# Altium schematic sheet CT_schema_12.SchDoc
size 386 x 278 mm
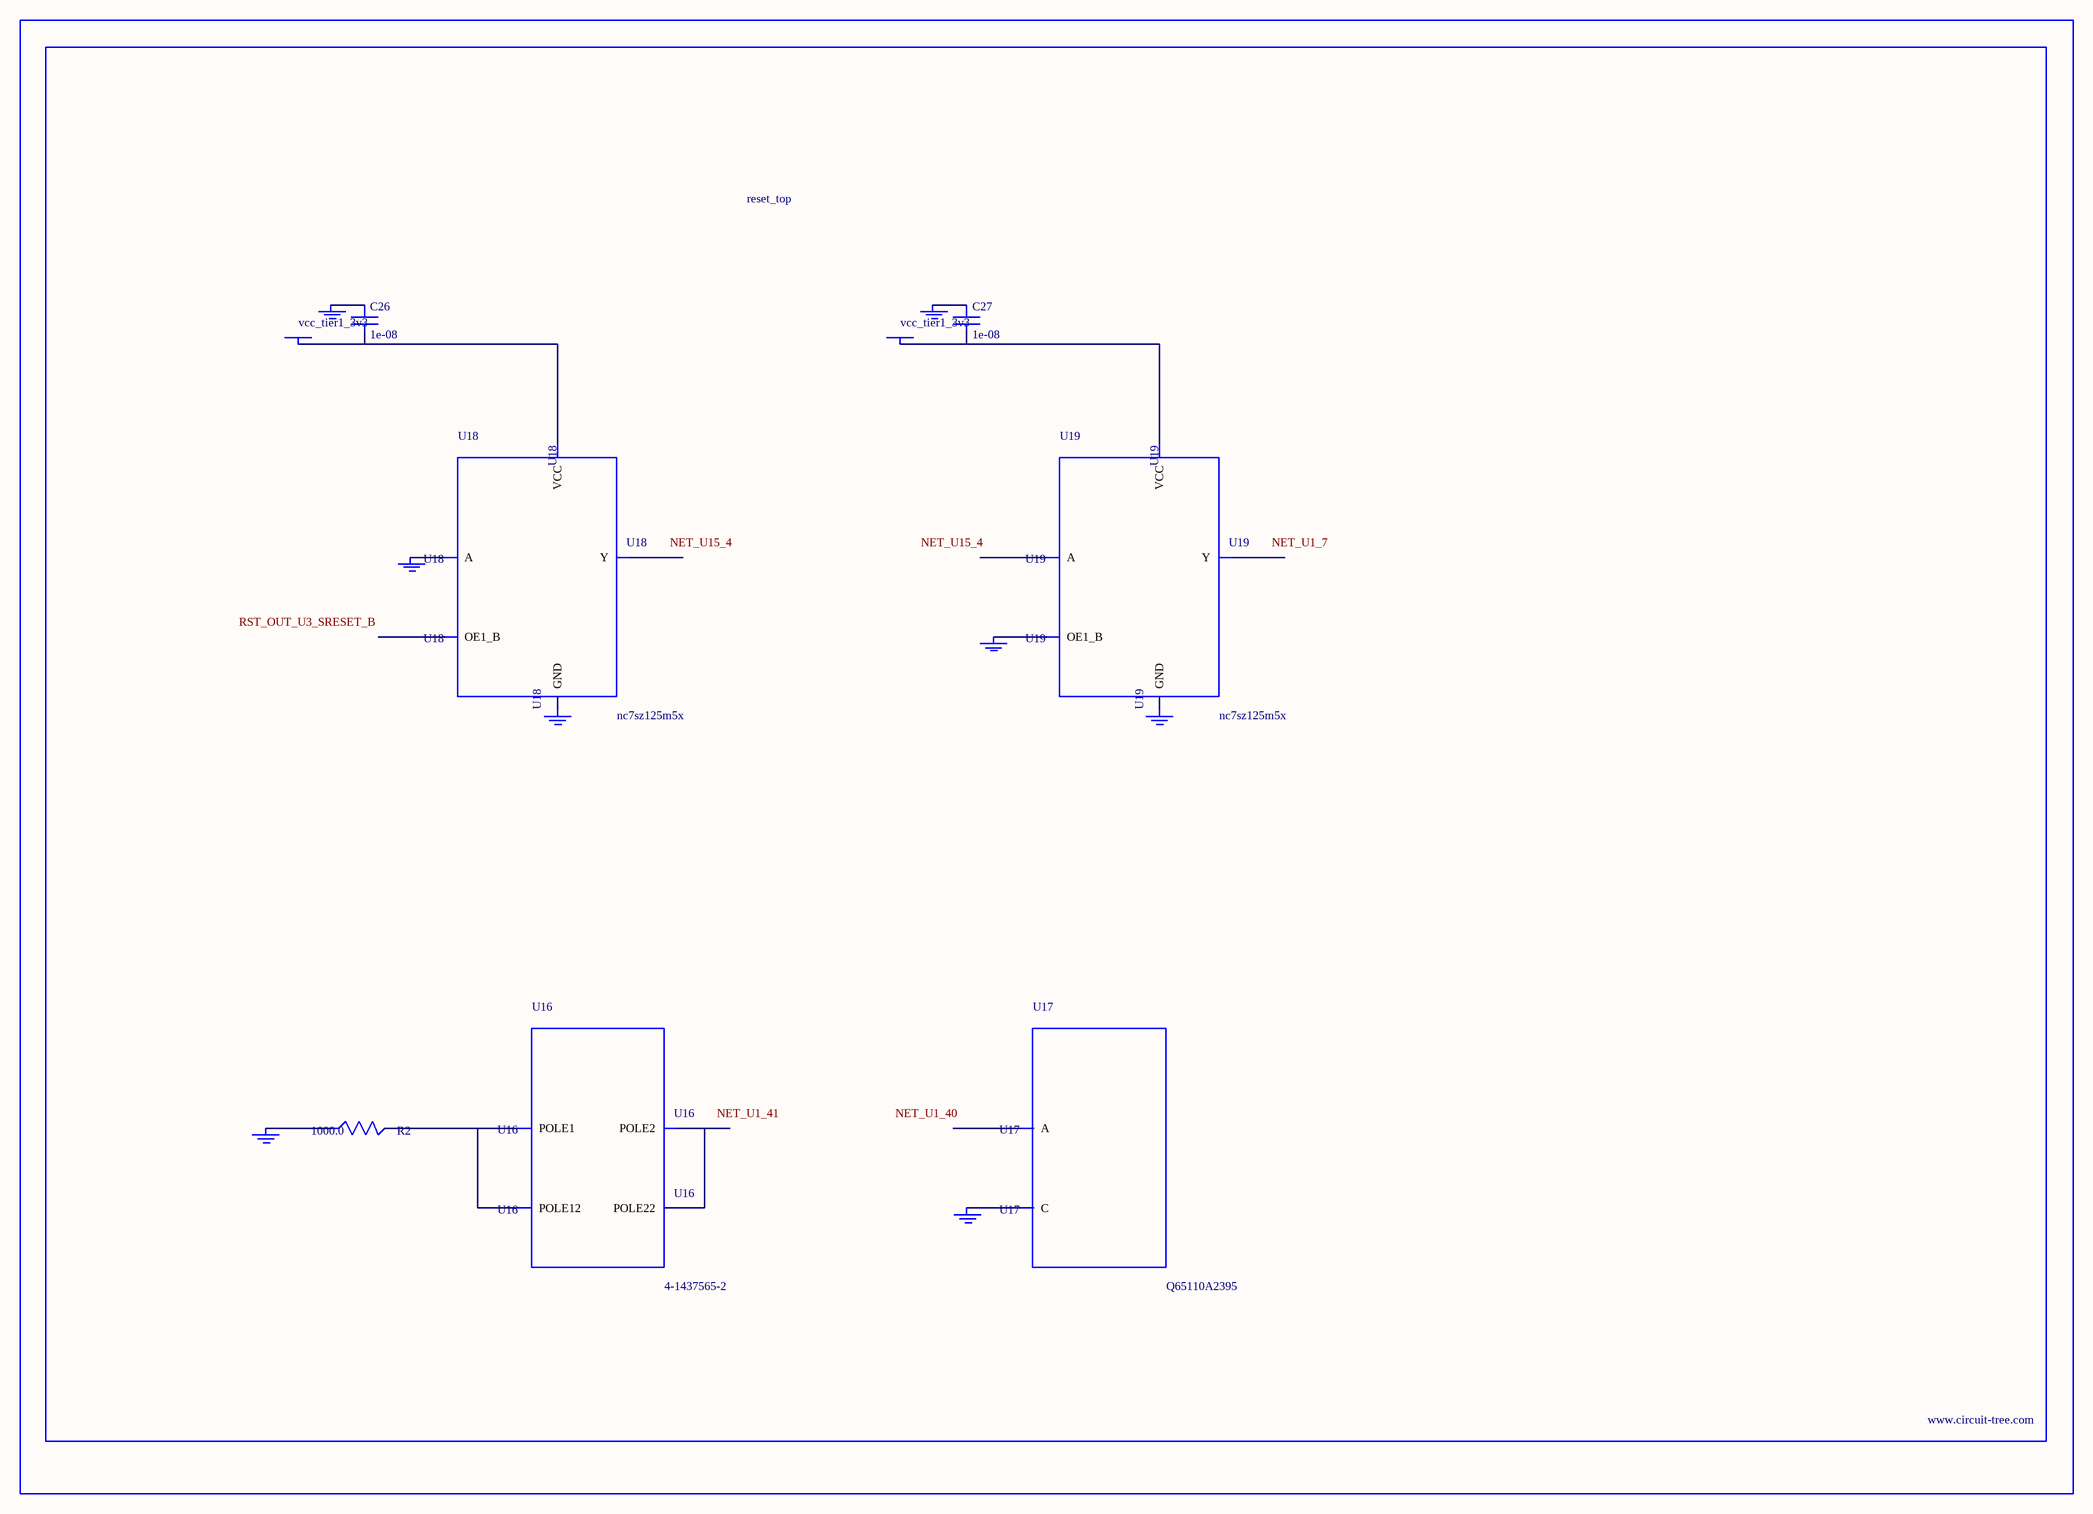
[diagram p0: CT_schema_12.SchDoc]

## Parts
BORDER11  (no value)
C26  1e-08  [C0402]
C27  1e-08  [C0402]
GND_INSTANCE_11_0  (no value)
GND_INSTANCE_11_1  (no value)
GND_INSTANCE_11_2  (no value)
GND_INSTANCE_11_3  (no value)
GND_INSTANCE_11_4  (no value)
GND_INSTANCE_11_5  (no value)
GND_INSTANCE_11_6  (no value)
GND_INSTANCE_11_7  (no value)
POWER_INSTANCE_11_0  vcc_tier1_3v3
POWER_INSTANCE_11_1  vcc_tier1_3v3
R2  1000.0  [R0603]
U16  4-1437565-2  [SW_4-1437565-2]
U17  Q65110A2395  [LGM67K-G1J2-24-Z]
U18  nc7sz125m5x  [NC7SZ125M5X]
U19  nc7sz125m5x  [NC7SZ125M5X]

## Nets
NetC26_1: C26.1 GND_INSTANCE_11_2.0(GND)
NetC26_2: C26.2 POWER_INSTANCE_11_0.0(PWR) U18.5(VCC)
NetC27_1: C27.1 GND_INSTANCE_11_5.0(GND)
NetC27_2: C27.2 POWER_INSTANCE_11_1.0(PWR) U19.5(VCC)
NetGND_INSTANCE_11_0_0: GND_INSTANCE_11_0.0(GND) R2.1
NetGND_INSTANCE_11_1_0: GND_INSTANCE_11_1.0(GND) U17.C
NetGND_INSTANCE_11_3_0: GND_INSTANCE_11_3.0(GND) U18.2(A)
NetGND_INSTANCE_11_4_0: GND_INSTANCE_11_4.0(GND) U18.3(GND)
NetGND_INSTANCE_11_6_0: GND_INSTANCE_11_6.0(GND) U19.1(OE1_B)
NetGND_INSTANCE_11_7_0: GND_INSTANCE_11_7.0(GND) U19.3(GND)
NetR2_2: R2.2 U16.1(POLE1) U16.2(POLE12)
NetU16_3: U16.3(POLE2) U16.4(POLE22)

Not connected (* = marked no-connect by the designer): U17 A; U18 1(OE1_B) 4(Y); U19 2(A) 4(Y)

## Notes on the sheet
- Labels drawn without touching a wire or pin: NET_U1_7, NET_U1_40, NET_U1_41, NET_U15_4, RST_OUT_U3_SRESET_B

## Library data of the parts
BORDER11 = BORDER_PAGE11
C26 C27 = C0402C103K3RAC
GND_INSTANCE_11_0-GND_INSTANCE_11_7 = GND
POWER_INSTANCE_11_0 POWER_INSTANCE_11_1 = PWR
R2 = RC0603JR-071KL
